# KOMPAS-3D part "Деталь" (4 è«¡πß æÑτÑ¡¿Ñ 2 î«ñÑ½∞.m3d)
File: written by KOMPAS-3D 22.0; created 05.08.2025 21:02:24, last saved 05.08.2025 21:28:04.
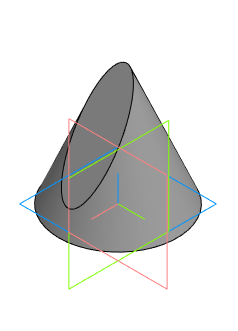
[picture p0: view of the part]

Document properties: Автор: user; Полное имя файла: G:\08 05 вторник\2025 НГ Лаб работы\Лаб 4 Сечение конуса\4 Модели\4 Конус Сечение 4 Модель.m3d

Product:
- Part/product: Деталь
    Масса: 0.494645

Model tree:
1. Эскиз:1
2. Элемент вращения:1
     Угол 1 = 360
3. Эскиз:2
4. Элемент выдавливания:1
     Расстояние 1 = 30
